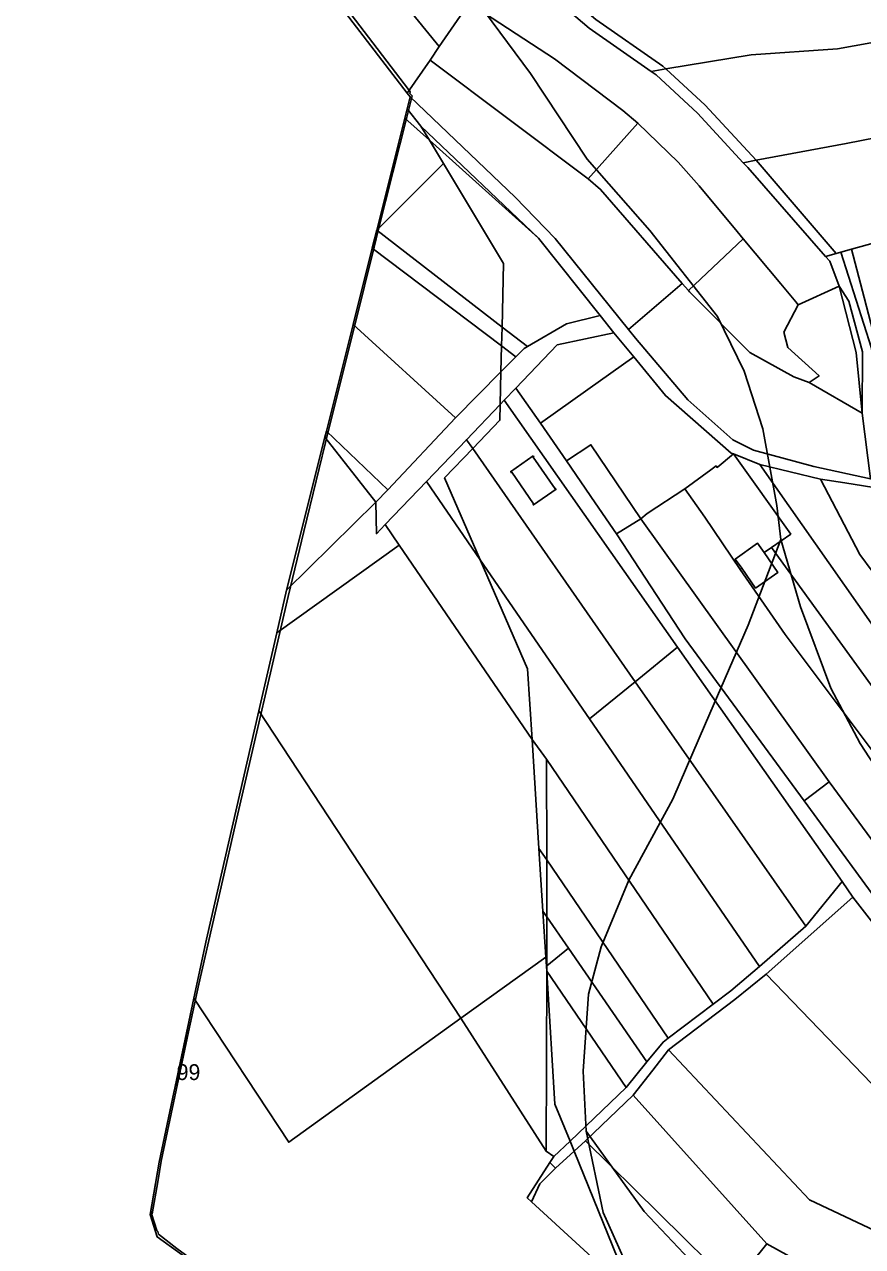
# Model space of a CAD drawing. Extents: x -535894 to -532834, y -1165802 to -1163645.
# Drawn here: x -535269.9 to -535005.1, y -1165457.3 to -1165071.2 of the extents above; entities that cross this region are included whole.
import ezdxf

# ---------------------------------------------------------------- set-up
doc = ezdxf.new("R2010")
doc.units = 0
for name, color, linetype in [('95560013', 7, 'Continuous'), ('95590013', 7, 'Continuous'), ('95600013', 7, 'Continuous'), ('95610013', 7, 'Continuous'), ('95640013', 7, 'Continuous'), ('95660013', 7, 'Continuous')]:
    doc.layers.add(name, color=color, linetype=linetype)

msp = doc.modelspace()

# ---------------------------------------------------------------- linework, layer by layer
at = {"layer": '95560013'}
for points in [[(-534688.38, -1164981.11), (-534659.02, -1164979.39), (-534659.81, -1164981.95), (-534655.57, -1165032.56), (-534724.66, -1165029.47), (-534765.23, -1165030.38), (-534811.29, -1165033.87), (-534889.63, -1165046.79), (-534952.44, -1165063.23), (-534984.36, -1165073.72), (-535013.06, -1165078.91), (-535040.34, -1165080.81), (-535067.25, -1165085.28), (-535068.17, -1165084.42), (-535089.33, -1165069.61), (-535106.82, -1165054.65), (-535020.48, -1165037.2), (-534961.7, -1165023.3), (-534911.68, -1165008.4), (-534840.9, -1164993.6), (-534776.34, -1164986.27)], [(-534765.23, -1165030.38), (-534724.66, -1165029.47), (-534655.57, -1165032.56), (-534654.53, -1165060.65), (-534677.01, -1165058.08), (-534733.66, -1165051.62), (-534773.14, -1165052.16), (-534797.08, -1165055.15), (-534876.98, -1165070.12), (-534985.58, -1165103.95), (-535010.28, -1165108.81), (-535038.78, -1165114.13), (-535054.81, -1165096.75), (-535067.25, -1165085.28), (-535040.34, -1165080.81), (-535013.06, -1165078.91), (-534984.36, -1165073.72), (-534952.44, -1165063.23), (-534889.63, -1165046.79), (-534811.29, -1165033.87)], [(-535158.81, -1165222.18), (-535187.04, -1165249.93), (-535174.94, -1165201.58)], [(-535073.16, -1165225.77), (-535061.21, -1165217.88), (-535054.98, -1165226.88), (-535043.78, -1165243.38), (-535029.52, -1165263.9), (-534998.93, -1165304.82), (-534979.45, -1165330.89), (-534948.88, -1165373.43), (-534922.19, -1165413.88), (-534938.7, -1165417.09), (-534970.98, -1165370.34), (-534998.37, -1165333.97), (-535015.67, -1165310.49), (-535075.17, -1165227.4)]]:
    msp.add_lwpolyline(points, close=True, dxfattribs=at)
msp.add_lwpolyline([(-534734.34, -1165074.8), (-534763.47, -1165073.76), (-534794.45, -1165076.97), (-534819.92, -1165081.13), (-534823.22, -1165081.65), (-534869.07, -1165092.98), (-534889.43, -1165100.93), (-534912.55, -1165110.44), (-534943.81, -1165122.47), (-534959.64, -1165128.57), (-534975.01, -1165132.85), (-534993.62, -1165138.05), (-534997.55, -1165139.14), (-535008.66, -1165142.24), (-535012, -1165143.18), (-535013.47, -1165143.59), (-535038.78, -1165114.13), (-535010.28, -1165108.81), (-534985.58, -1165103.95), (-534876.98, -1165070.12)], dxfattribs=at)
at = {"layer": '95590013'}
for points in [[(-535076.07, -1165102.38), (-535063.36, -1165114.7), (-535056.76, -1165122.24), (-535044.77, -1165136.59), (-535042.84, -1165138.9), (-535060.13, -1165155.29), (-535062.12, -1165153.01), (-535087.88, -1165123.32), (-535091.8, -1165120.03)], [(-535042.84, -1165138.9), (-535030.91, -1165153.2), (-535026.15, -1165158.85), (-535025.48, -1165159.77), (-535030.02, -1165168.39), (-535028.68, -1165173.31), (-535018.83, -1165182.23), (-535022.03, -1165184.29), (-535026.83, -1165182.51), (-535040.74, -1165174.89), (-535059.81, -1165155.66), (-535060.13, -1165155.29)], [(-535008.66, -1165142.24), (-534997.55, -1165139.14), (-534979.02, -1165176.38), (-534995.45, -1165182.69), (-534993.46, -1165188.33), (-534994.83, -1165188.64), (-534990.02, -1165206.28), (-534988.07, -1165212.89), (-534986.89, -1165216.91), (-534997.45, -1165215.46), (-535000.3, -1165193.52), (-535000.44, -1165173.68), (-535004.66, -1165157.53)], [(-535012, -1165143.18), (-535008.66, -1165142.24), (-535004.66, -1165157.53), (-535000.44, -1165173.68), (-535000.3, -1165193.52), (-535002.34, -1165173.49)], [(-535101.55, -1165172.42), (-535083.66, -1165168.59), (-535077.41, -1165176.22), (-535091.93, -1165186.56), (-535106.85, -1165197.19), (-535114.67, -1165186.14)], [(-535114.59, -1165176.22), (-535119.34, -1165180.99), (-535119.15, -1165172.77)], [(-535033.85, -1165236.42), (-534997.4, -1165286.9), (-534989.64, -1165297.88), (-534998.93, -1165304.82), (-535029.52, -1165263.9), (-535043.78, -1165243.38), (-535043.28, -1165243.03), (-535038.89, -1165249.3), (-535031.86, -1165244.32), (-535036.23, -1165238.09)]]:
    msp.add_lwpolyline(points, close=True, dxfattribs=at)
at = {"layer": '95600013'}
for points in [[(-535037.55, -1165210.25), (-534958.11, -1165323.54), (-534923.85, -1165374.08), (-534903.47, -1165406.8), (-534912.22, -1165410.87), (-534937.49, -1165371.67), (-534989.64, -1165297.88), (-534997.4, -1165286.9), (-535033.85, -1165236.42), (-535027.81, -1165232.2), (-535045.87, -1165206.9)], [(-535018.41, -1165214.83), (-535006.02, -1165238.65), (-534986.55, -1165265), (-534939.83, -1165336.12), (-534921.55, -1165360.67), (-534895.49, -1165403.09), (-534899.67, -1165405.03), (-534903.47, -1165406.8), (-534923.85, -1165374.08), (-534958.11, -1165323.54), (-535037.55, -1165210.25)], [(-535010.74, -1165216.05), (-534998.89, -1165217.93), (-534910.74, -1165344.78), (-534877.22, -1165393.33), (-534885.71, -1165398.12), (-534889.94, -1165400.51), (-534895.49, -1165403.09), (-534921.55, -1165360.67), (-534939.83, -1165336.12), (-534986.55, -1165265), (-535006.02, -1165238.65), (-535018.41, -1165214.83)]]:
    msp.add_lwpolyline(points, close=True, dxfattribs=at)
at = {"layer": '95610013'}
for points in [[(-535220.19, -1164916.49), (-535192.57, -1164975.97), (-535181.9, -1164992.48), (-535168.5, -1165015.08), (-535167.09, -1165017.44), (-535153.27, -1165037.38), (-535141.65, -1165049.71), (-535129.39, -1165064.5), (-535138.85, -1165078.22), (-535172.47, -1165036.89), (-535179.28, -1165027.8), (-535211.27, -1164985.05), (-535243.3, -1164928.03), (-535231.36, -1164922.07)], [(-535179.28, -1165027.8), (-535172.47, -1165036.89), (-535138.85, -1165078.22), (-535141.75, -1165082.45), (-535149, -1165092.96), (-535191.37, -1165037.5)], [(-535138.85, -1165078.22), (-535129.39, -1165064.5), (-535102.38, -1165082.03), (-535080.8, -1165098.36), (-535076.07, -1165102.38), (-535091.8, -1165120.03), (-535141.75, -1165082.45)], [(-535141.75, -1165082.45), (-535091.8, -1165120.03), (-535087.88, -1165123.32), (-535062.12, -1165153.01), (-535079.07, -1165167.61), (-535102.26, -1165138.81), (-535114.86, -1165125.73), (-535148.04, -1165094.04), (-535149, -1165092.96)], [(-535141.94, -1165107.81), (-535144.62, -1165103.35), (-535107.51, -1165138.7)], [(-535137.53, -1165115.16), (-535141.94, -1165107.81), (-535107.51, -1165138.7), (-535088.02, -1165163.17), (-535098.68, -1165165.83), (-535111, -1165173.01), (-535119.01, -1165166.82), (-535118.55, -1165146.77)], [(-535060.13, -1165155.29), (-535059.81, -1165155.66), (-535040.74, -1165174.89), (-535026.83, -1165182.51), (-535022.03, -1165184.29), (-535005.25, -1165194.06), (-535002.66, -1165214.75), (-535020.54, -1165210.89), (-535039.58, -1165205.73), (-535046.07, -1165202.42), (-535060.28, -1165189.76), (-535076.86, -1165170.35), (-535079.07, -1165167.61), (-535062.12, -1165153.01)], [(-535119.57, -1165191.26), (-535118.3, -1165189.93), (-535063.56, -1165267.97), (-535076.93, -1165278.88), (-535128.27, -1165205.23), (-535119.69, -1165196.25)], [(-535119.69, -1165196.25), (-535128.27, -1165205.23), (-535130.24, -1165202.4), (-535119.57, -1165191.26)], [(-535128.27, -1165205.23), (-535137.13, -1165214.5), (-535125.87, -1165240.38), (-535142.88, -1165215.62), (-535130.24, -1165202.4)], [(-535137.13, -1165214.5), (-535128.27, -1165205.23), (-535076.93, -1165278.88), (-535091.37, -1165290.64), (-535125.87, -1165240.38)], [(-535090.91, -1165203.99), (-535075.17, -1165227.4), (-535082.81, -1165232.15), (-535089.57, -1165222.34), (-535098.68, -1165209.08)], [(-535109.14, -1165207.55), (-535116.32, -1165212.52), (-535116.14, -1165212.77), (-535115.94, -1165212.64), (-535109.06, -1165222.62), (-535109.26, -1165222.75), (-535109.09, -1165223.01), (-535101.91, -1165218.04), (-535102.07, -1165217.82), (-535102.27, -1165217.95), (-535109.17, -1165207.94), (-535108.98, -1165207.79)], [(-535082.81, -1165232.15), (-535075.17, -1165227.4), (-535015.67, -1165310.49), (-535023.58, -1165316.51), (-535061.16, -1165265.28)], [(-535110.91, -1165274.78), (-535125.87, -1165240.38), (-535091.37, -1165290.64), (-535037.72, -1165368.79), (-535046.68, -1165376.54), (-535052.32, -1165380.79), (-535104.97, -1165303.3), (-535109.49, -1165297.17)], [(-535076.93, -1165278.88), (-535063.56, -1165267.97), (-535011.6, -1165342.03), (-535023.08, -1165356.13)], [(-535091.37, -1165290.64), (-535076.93, -1165278.88), (-535023.08, -1165356.13), (-535037.72, -1165368.79)], [(-535104.88, -1165335.18), (-535104.97, -1165303.3), (-535052.32, -1165380.79), (-535066.56, -1165391.53)], [(-535015.67, -1165310.49), (-534998.37, -1165333.97), (-534970.98, -1165370.34), (-534938.7, -1165417.09), (-534947.37, -1165418.77), (-534995.2, -1165355.23), (-535023.58, -1165316.51)], [(-535104.84, -1165353.15), (-535104.88, -1165335.18), (-535066.56, -1165391.53), (-535068.13, -1165392.72), (-535073.24, -1165399.01), (-535098.04, -1165363.02)], [(-535035.57, -1165371.22), (-535008.17, -1165346.93), (-534969.17, -1165397.16), (-534950.64, -1165422.73), (-534946.88, -1165427.7), (-534976.33, -1165433.85), (-534991.19, -1165417.39)], [(-535104.84, -1165353.15), (-535098.04, -1165363.02), (-535104.9, -1165368.65)], [(-535104.9, -1165368.65), (-535098.04, -1165363.02), (-535073.24, -1165399.01), (-535079.82, -1165407.1), (-535104.9, -1165370.29)], [(-535104.78, -1165372.28), (-535102.28, -1165412.28), (-535097.53, -1165423.98), (-535102.66, -1165428.89), (-535105.08, -1165427.18), (-535104.9, -1165370.29)], [(-535104.78, -1165372.28), (-535104.9, -1165370.29), (-535079.82, -1165407.1), (-535097.53, -1165423.98), (-535102.28, -1165412.28)], [(-535045.46, -1165379.26), (-535035.57, -1165371.22), (-534991.19, -1165417.39), (-534976.33, -1165433.85), (-534971.78, -1165438.88), (-534963.24, -1165444.04), (-534963.38, -1165463.4), (-534980.62, -1165462.08), (-535021.86, -1165442.54), (-535066.38, -1165395.21)], [(-535071.39, -1165401.58), (-535066.38, -1165395.21), (-535021.86, -1165442.54), (-534980.62, -1165462.08), (-534963.38, -1165463.4), (-534962.06, -1165475.26), (-534960.76, -1165486.97), (-534989.98, -1165481.49), (-535035.38, -1165456.43), (-535077.63, -1165409.51)], [(-535092.6, -1165423.96), (-535077.63, -1165409.51), (-535035.38, -1165456.43), (-535046.07, -1165469.78)], [(-535096.21, -1165427.21), (-535092.6, -1165423.96), (-535046.07, -1165469.78), (-535035.38, -1165456.43), (-534989.98, -1165481.49), (-534960.76, -1165486.97), (-534959.91, -1165494.58), (-534953.71, -1165520.27), (-535000.04, -1165522.28), (-535001.7, -1165503.8), (-535042.71, -1165481.75), (-535059.01, -1165466.27), (-535076.09, -1165474.03), (-535077.85, -1165472.41)], [(-535102.15, -1165432.54), (-535096.21, -1165427.21), (-535077.85, -1165472.41), (-535109.7, -1165443.14), (-535107.08, -1165437.55)], [(-535102.15, -1165432.54), (-535107.08, -1165437.55), (-535109.7, -1165443.14), (-535111.02, -1165441.92), (-535103.85, -1165430.74)]]:
    msp.add_lwpolyline(points, close=True, dxfattribs=at)
msp.add_lwpolyline([(-535111.17, -1165055.54), (-535091.48, -1165072.37), (-535071.93, -1165086.06), (-535070.36, -1165087.15), (-535057.29, -1165099.23), (-535042.82, -1165114.91), (-535041.39, -1165116.45), (-535016.81, -1165144.52), (-535015.48, -1165146.04), (-535012.56, -1165153.94), (-535025.48, -1165159.77), (-535026.15, -1165158.85), (-535030.91, -1165153.2), (-535042.84, -1165138.9), (-535044.77, -1165136.59), (-535056.76, -1165122.24), (-535063.36, -1165114.7), (-535076.07, -1165102.38), (-535080.8, -1165098.36), (-535102.38, -1165082.03), (-535129.39, -1165064.5)], dxfattribs=at)
at = {"layer": '95640013'}
for points in [[(-535111.17, -1165055.54), (-535106.82, -1165054.65), (-535089.33, -1165069.61), (-535068.17, -1165084.42), (-535067.25, -1165085.28), (-535071.93, -1165086.06), (-535091.48, -1165072.37)], [(-535071.93, -1165086.06), (-535067.25, -1165085.28), (-535054.81, -1165096.75), (-535038.78, -1165114.13), (-535042.82, -1165114.91), (-535057.29, -1165099.23), (-535070.36, -1165087.15)], [(-535141.94, -1165107.81), (-535137.53, -1165115.16), (-535158.58, -1165136.22), (-535149.73, -1165100.83)], [(-535149.73, -1165100.83), (-535148.98, -1165097.84), (-535144.62, -1165103.35), (-535141.94, -1165107.81)], [(-535158.58, -1165136.22), (-535137.53, -1165115.16), (-535118.55, -1165146.77), (-535119.01, -1165166.82)], [(-535042.82, -1165114.91), (-535038.78, -1165114.13), (-535013.47, -1165143.59), (-535016.81, -1165144.52), (-535041.39, -1165116.45)], [(-535160, -1165141.88), (-535158.58, -1165136.22), (-535119.01, -1165166.82), (-535119.15, -1165172.77)], [(-535166.05, -1165166.05), (-535160, -1165141.88), (-535119.15, -1165172.77), (-535119.34, -1165180.99), (-535133.73, -1165195.47)], [(-535013.47, -1165143.59), (-535012, -1165143.18), (-535002.34, -1165173.49), (-535000.3, -1165193.52), (-534997.45, -1165215.46), (-535000.46, -1165215.04), (-535002.66, -1165214.75), (-535005.25, -1165194.06), (-535005.19, -1165174.65), (-535009.44, -1165158.65), (-535012.56, -1165153.94), (-535015.48, -1165146.04), (-535016.81, -1165144.52)], [(-535025.48, -1165159.77), (-535012.56, -1165153.94), (-535007.1, -1165174.89), (-535005.25, -1165194.06), (-535022.03, -1165184.29), (-535018.83, -1165182.23), (-535028.68, -1165173.31), (-535030.02, -1165168.39)], [(-535009.44, -1165158.65), (-535005.19, -1165174.65), (-535005.25, -1165194.06), (-535007.1, -1165174.89), (-535012.56, -1165153.94)], [(-535098.68, -1165165.83), (-535088.02, -1165163.17), (-535083.66, -1165168.59), (-535101.55, -1165172.42), (-535114.67, -1165186.14), (-535118.3, -1165189.93), (-535119.57, -1165191.26), (-535119.34, -1165180.99), (-535114.59, -1165176.22), (-535111.96, -1165173.57), (-535111, -1165173.01)], [(-535133.73, -1165195.47), (-535155.07, -1165218.2), (-535174.47, -1165199.7), (-535166.05, -1165166.05)], [(-535119.15, -1165172.77), (-535119.01, -1165166.82), (-535111, -1165173.01), (-535111.96, -1165173.57), (-535114.59, -1165176.22)], [(-535077.41, -1165176.22), (-535067.39, -1165188.44), (-535046.59, -1165206.68), (-535045.87, -1165206.9), (-535051.06, -1165211.14), (-535051.41, -1165210.68), (-535053.1, -1165211.91), (-535061.21, -1165217.88), (-535073.16, -1165225.77), (-535075.17, -1165227.4), (-535090.91, -1165203.99), (-535098.68, -1165209.08), (-535106.85, -1165197.19), (-535091.93, -1165186.56)], [(-535119.57, -1165191.26), (-535130.24, -1165202.4), (-535142.88, -1165215.62), (-535155.91, -1165229.23), (-535158.69, -1165232.13), (-535158.81, -1165222.18), (-535155.07, -1165218.2), (-535133.73, -1165195.47), (-535119.34, -1165180.99)], [(-535118.3, -1165189.93), (-535114.67, -1165186.14), (-535106.85, -1165197.19), (-535098.68, -1165209.08), (-535089.57, -1165222.34), (-535082.81, -1165232.15), (-535061.16, -1165265.28), (-535023.58, -1165316.51), (-534995.2, -1165355.23), (-534947.37, -1165418.77), (-534938.7, -1165417.09), (-534922.19, -1165413.88), (-534912.22, -1165410.87), (-534903.47, -1165406.8), (-534899.67, -1165405.03), (-534895.63, -1165410.85), (-534918.48, -1165416.99), (-534950.64, -1165422.73), (-534969.17, -1165397.16), (-535008.17, -1165346.93), (-535011.6, -1165342.03), (-535063.56, -1165267.97)], [(-535174.94, -1165201.58), (-535174.47, -1165199.7), (-535155.07, -1165218.2), (-535158.81, -1165222.18)], [(-535109.14, -1165207.55), (-535108.98, -1165207.79), (-535109.17, -1165207.94), (-535102.27, -1165217.95), (-535102.07, -1165217.82), (-535101.91, -1165218.04), (-535109.09, -1165223.01), (-535109.26, -1165222.75), (-535109.06, -1165222.62), (-535115.94, -1165212.64), (-535116.14, -1165212.77), (-535116.32, -1165212.52)], [(-535051.06, -1165211.14), (-535045.87, -1165206.9), (-535027.81, -1165232.2), (-535033.85, -1165236.42), (-535036.23, -1165238.09), (-535038.3, -1165235.12), (-535045.33, -1165240.11), (-535043.28, -1165243.03), (-535043.78, -1165243.38), (-535054.98, -1165226.88), (-535061.21, -1165217.88), (-535053.1, -1165211.91), (-535051.41, -1165210.68)], [(-535155.91, -1165229.23), (-535142.88, -1165215.62), (-535125.87, -1165240.38), (-535110.91, -1165274.78), (-535109.49, -1165297.17), (-535151.45, -1165235.77)], [(-535158.69, -1165232.13), (-535155.91, -1165229.23), (-535151.45, -1165235.77), (-535190.12, -1165263.37), (-535187.04, -1165249.93), (-535158.81, -1165222.18)], [(-535151.45, -1165235.77), (-535109.49, -1165297.17), (-535107.33, -1165331.56), (-535106.09, -1165351.32), (-535105.18, -1165365.89), (-535131.97, -1165385.19), (-535195.8, -1165288.07), (-535190.12, -1165263.37)], [(-535038.3, -1165235.12), (-535036.23, -1165238.09), (-535031.86, -1165244.32), (-535038.89, -1165249.3), (-535043.28, -1165243.03), (-535045.33, -1165240.11)], [(-535195.8, -1165288.07), (-535131.97, -1165385.19), (-535186.38, -1165424.39), (-535216.3, -1165378.85), (-535212.35, -1165360.19)], [(-535104.97, -1165303.3), (-535104.88, -1165335.18), (-535107.33, -1165331.56), (-535109.49, -1165297.17)], [(-535107.33, -1165331.56), (-535104.88, -1165335.18), (-535104.84, -1165353.15), (-535106.09, -1165351.32)], [(-535011.6, -1165342.03), (-535008.17, -1165346.93), (-535035.57, -1165371.22), (-535045.46, -1165379.26), (-535066.38, -1165395.21), (-535071.39, -1165401.58), (-535077.63, -1165409.51), (-535092.6, -1165423.96), (-535096.21, -1165427.21), (-535097.53, -1165423.98), (-535079.82, -1165407.1), (-535073.24, -1165399.01), (-535068.13, -1165392.72), (-535066.56, -1165391.53), (-535052.32, -1165380.79), (-535046.68, -1165376.54), (-535037.72, -1165368.79), (-535023.08, -1165356.13)], [(-535106.09, -1165351.32), (-535104.84, -1165353.15), (-535104.9, -1165368.65), (-535104.9, -1165370.29), (-535105.18, -1165365.89)], [(-535104.9, -1165370.29), (-535105.08, -1165427.18), (-535131.97, -1165385.19), (-535105.18, -1165365.89)], [(-535131.97, -1165385.19), (-535105.08, -1165427.18), (-535102.66, -1165428.89), (-535103.85, -1165430.74), (-535111.02, -1165441.92), (-535109.7, -1165443.14), (-535077.85, -1165472.41), (-535076.26, -1165476.34), (-535087.18, -1165485.86), (-535153.29, -1165531.56), (-535165.68, -1165517.45), (-535180.07, -1165495.46), (-535211.33, -1165466.2), (-535227.94, -1165454.25), (-535230.12, -1165447.22), (-535227.28, -1165430.67), (-535216.3, -1165378.85), (-535186.38, -1165424.39)], [(-535096.21, -1165427.21), (-535102.15, -1165432.54), (-535103.85, -1165430.74), (-535102.66, -1165428.89), (-535097.53, -1165423.98)]]:
    msp.add_lwpolyline(points, close=True, dxfattribs=at)
msp.add_lwpolyline([(-534998.89, -1165217.93), (-535010.74, -1165216.05), (-535018.41, -1165214.83), (-535037.55, -1165210.25), (-535045.87, -1165206.9), (-535046.59, -1165206.68), (-535067.39, -1165188.44), (-535077.41, -1165176.22), (-535083.66, -1165168.59), (-535088.02, -1165163.17), (-535107.51, -1165138.7), (-535144.62, -1165103.35), (-535148.98, -1165097.84), (-535148.04, -1165094.04), (-535114.86, -1165125.73), (-535102.26, -1165138.81), (-535079.07, -1165167.61), (-535076.86, -1165170.35), (-535060.28, -1165189.76), (-535046.07, -1165202.42), (-535039.58, -1165205.73), (-535020.54, -1165210.89), (-535002.66, -1165214.75)], dxfattribs=at)
at = {"layer": '95660013'}
for points in [[(-535269.853, -1164932.956), (-535148.539, -1165091.751), (-535147.971, -1165092.495), (-535148.097, -1165093.014), (-535147.427, -1165093.765), (-535148.373, -1165097.563), (-535149.117, -1165100.549), (-535157.973, -1165135.942), (-535159.387, -1165141.6), (-535165.434, -1165165.767), (-535173.855, -1165199.418), (-535181.592, -1165231.374), (-535186.572, -1165251.945), (-535202.428, -1165320.572), (-535208.053, -1165345.043), (-535209.623, -1165351.873), (-535214.803, -1165374.411), (-535217.987, -1165389.45), (-535226.653, -1165430.387), (-535227.77, -1165436.903), (-535229.489, -1165446.933), (-535229.697, -1165446.939), (-535229.937, -1165446.154), (-535227.28, -1165430.67), (-535222.616, -1165408.657), (-535220.965, -1165401.364), (-535221.656, -1165404.128), (-535216.3, -1165378.85), (-535212.35, -1165360.19), (-535195.8, -1165288.07), (-535190.12, -1165263.37), (-535187.04, -1165249.93), (-535174.94, -1165201.58), (-535174.47, -1165199.7), (-535166.05, -1165166.05), (-535160, -1165141.88), (-535158.58, -1165136.22), (-535149.73, -1165100.83), (-535148.98, -1165097.84), (-535148.04, -1165094.04), (-535149, -1165092.96), (-535191.37, -1165037.5)], [(-535221.739, -1165457.976), (-535227.491, -1165453.394), (-535227.757, -1165452.533), (-535228.059, -1165452.29), (-535229.697, -1165446.939), (-535229.489, -1165446.933), (-535227.77, -1165436.903), (-535226.653, -1165430.387), (-535217.987, -1165389.45), (-535214.803, -1165374.411), (-535209.623, -1165351.873), (-535208.053, -1165345.043), (-535202.428, -1165320.572), (-535186.572, -1165251.945), (-535181.592, -1165231.374), (-535173.855, -1165199.418), (-535165.434, -1165165.767), (-535159.387, -1165141.6), (-535157.973, -1165135.942), (-535149.117, -1165100.549), (-535148.373, -1165097.563), (-535147.427, -1165093.765), (-535148.097, -1165093.014), (-535147.971, -1165092.495), (-535148.539, -1165091.751), (-535269.853, -1164932.956)], [(-535124.571, -1165067.131), (-535110.05, -1165086.73), (-535092.06, -1165113.81), (-535072.31, -1165136.27), (-535050.959, -1165163.5), (-535042.52, -1165180.7), (-535036.666, -1165198.943), (-535032.17, -1165223.23), (-535030.89, -1165233.98), (-535041.257, -1165261.04), (-535054.7, -1165292.04), (-535065.06, -1165315.93), (-535078.92, -1165341.58), (-535087.68, -1165362.6), (-535091.66, -1165377.57), (-535093.41, -1165401.94), (-535092.45, -1165420.9), (-535087.04, -1165446.54), (-535075.396, -1165472.696)], [(-535000.001, -1165307.403), (-535005.89, -1165298.41), (-535015.12, -1165280.89), (-535024.68, -1165255.25), (-535030.89, -1165233.98), (-535032.17, -1165223.23), (-535036.666, -1165198.943), (-535042.52, -1165180.7), (-535050.959, -1165163.5), (-535072.31, -1165136.27), (-535092.06, -1165113.81), (-535110.05, -1165086.73), (-535124.571, -1165067.131)], [(-535054.39, -1165467.13), (-535074.14, -1165446.26), (-535092.45, -1165420.9), (-535093.41, -1165401.94), (-535091.66, -1165377.57), (-535087.68, -1165362.6), (-535078.92, -1165341.58), (-535065.06, -1165315.93), (-535054.7, -1165292.04), (-535041.257, -1165261.04), (-535030.89, -1165233.98), (-535024.68, -1165255.25), (-535015.12, -1165280.89), (-535005.89, -1165298.41), (-535000.001, -1165307.403)], [(-535075.396, -1165472.696), (-535087.04, -1165446.54), (-535092.45, -1165420.9), (-535074.14, -1165446.26), (-535054.39, -1165467.13)]]:
    msp.add_lwpolyline(points, dxfattribs=at)
for points in [[(-535220.965, -1165401.364), (-535222.616, -1165408.657), (-535221.656, -1165404.128)], [(-535197.513, -1165478.818), (-535197.667, -1165478.989), (-535211.33, -1165466.2), (-535227.94, -1165454.25), (-535230.12, -1165447.22), (-535229.937, -1165446.154), (-535229.697, -1165446.939), (-535228.059, -1165452.29), (-535227.757, -1165452.533), (-535227.491, -1165453.394), (-535221.739, -1165457.976), (-535214.364, -1165463.282), (-535209.32, -1165467.33), (-535205.939, -1165470.375), (-535197.241, -1165478.516)]]:
    msp.add_lwpolyline(points, close=True, dxfattribs=at)

# ---------------------------------------------------------------- texts
msp.add_text('99', height=5, rotation=360, dxfattribs=at).set_placement((-535221.746, -1165404.716))

doc.saveas('drawing.dxf')
